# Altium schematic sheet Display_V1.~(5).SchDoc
size A4; SheetNumber: 3; SheetTotal: 7
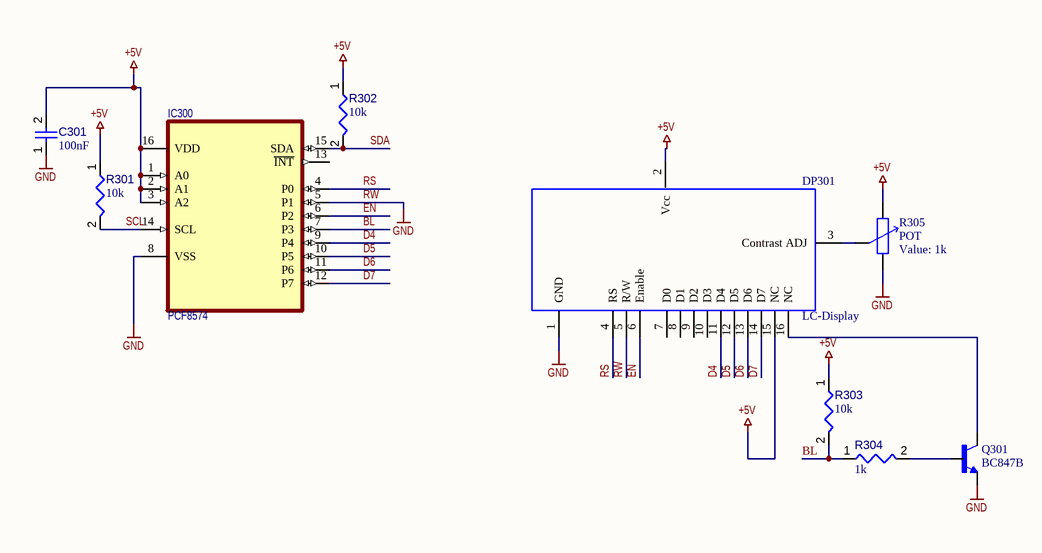
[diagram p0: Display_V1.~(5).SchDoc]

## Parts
C301  100nF  [CAPC1608X90X40NL10T20]
DP301  LC-Display  [V_THT_WM-C1610M]
IC300  PCF8574  [SO-16]
Q301  BC847B  [TRANS_BC847B]
R301  10k  [RESC1608X55X25ML10T15]
R302  10k  [RESC1608X55X25ML10T15]
R303  10k  [RESC1608X55X25ML10T15]
R304  value 1k  [RESC1608X55X25ML10T15]  (hidden comment: Resistor 1k +/-1% 0603 100 mW)
R305  POT  value 1k  [PT15]

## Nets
+5V: C301.2 DP301.2(Vcc) DP301.15(NC) IC300.1(A0) IC300.2(A1) IC300.3(A2) IC300.16(VDD) R301.1 R302.1 R303.1 R305.2
RW: C301.1 DP301.1(GND) DP301.5(R/W) IC300.5(P1) IC300.8(VSS) Q301.2(E) R305.1  [also labelled GND]
BL: IC300.7(P3) R303.2 R304.1
D4: DP301.11(D4) IC300.9(P4)
D5: DP301.12(D5) IC300.10(P5)
D6: DP301.13(D6) IC300.11(P6)
D7: DP301.14(D7) IC300.12(P7)
EN: DP301.6(Enable) IC300.6(P2)
RS: DP301.4(RS) IC300.4(P0)
SCL: IC300.14(SCL) R301.2
SDA: IC300.15(SDA) R302.2
NetDP301_3: DP301.3(Contrast_ADJ) R305.3
NetDP301_16: DP301.16(NC) Q301.3(C)
NetQ301_1: Q301.1(B) R304.2

Not connected (* = marked no-connect by the designer): DP301 7(D0) 8(D1) 9(D2) 10(D3); IC300 13(~{INT})

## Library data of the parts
C301 = CMP-001-00017-6: Chip Capacitor, 100 nF, +/- 10%, 50 V, 0603 (1608 Metric); Voltage Rating: 50V; Capacitor Type: Ceramic
DP301 = V_THT_LCD Modul: LCD
IC300 = IC_PCF8574: I/O Expander
Q301 = BC847B: BJT, SOT-23, 45V, 100mA, NPN, 0.25W, 150Â°C; MF: Diotec Semiconductor
R301-R303 = CMP-009-00017-5: Chip Resistor, 10 KOhm, +/- 1%, 01 W, -55 to 155 degC, 0603 (1608 Metric); Voltage Rating: 50V; Power: 100mW
R304 = CMP-009-00014-5: Chip Resistor, 1 KOhm, +/-1%, 0.1 W, -55 to 155 degC, 0603 (1608 Metric); Voltage Rating: 50V; Power: 100mW; Tolerance: 1%
R305 = POT: Potentiometer; Set Position: 0.5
